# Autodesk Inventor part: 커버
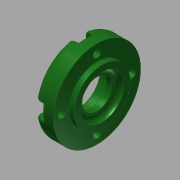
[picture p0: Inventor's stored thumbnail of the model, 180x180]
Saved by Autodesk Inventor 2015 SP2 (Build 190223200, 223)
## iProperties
Created: 2015-11
Part Number: 커버
Material: 알루미늄 6061
Document SubType Name: Modeling
Designer: mduedu
Density: 1 g/cm^3
Appearance: 매끄러움 - 짙은 산림 녹색
Author: mduedu
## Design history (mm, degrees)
sketch "스케치1"
  geometry: L1 (-7, 0)-(7, 0); L2 (-7, 0)-(-7, 25); L3 (-7, 25)-(4, 25); L4 (4, 25)-(4, 16); L5 (4, 16)-(7, 16); L6 (7, 16)-(7, 0); 2 further points
  constraints: 12 end point, 3 perpendicular, 2 parallel, 1 coincident, 1 horizontal, 1 midpoint
  dimensions: "d0" = 14 distance of L1.start L1.end; "d1" = 50 diameter of L3 L1; "d2" = 3 distance of L4.end L5.end; "d3" = 32 diameter of L5 L1
revolve "회전1" sketch "스케치1" stored, may be unused: angle "d4" = 90 deg
hole "구멍1" diameter "d7" = 25; stored, may be unused: countersink angle "d11" = 90 deg, drill point angle "d13" = 0 deg; dims "d5" = 10, "d6" = 10, "d8" = 6, "d9" = 4, "d10" = 2, "d12" = 3
hole "구멍2" diameter "d16" = 25; stored, may be unused: countersink angle "d20" = 90 deg, drill point angle "d22" = 0 deg; dims "d17" = 6, "d18" = 4, "d19" = 2, "d21" = 7.7, "d58" = 10, "d59" = 10
hole "구멍3" diameter "d25" = 17; stored, may be unused: countersink angle "d29" = 90 deg, drill point angle "d31" = 0 deg; dims "d23" = 10, "d24" = 10, "d26" = 6, "d27" = 4, "d28" = 2, "d30" = 4.2
chamfer "모따기1" distance "d32" = 0.6; stored, may be unused: second distance "d33" = 2, angle "d34" = 30 deg
fillet "모깎기1" dims "d35" = 0.3
fillet "모깎기2" dims "d36" = 3
fillet "모깎기3" dims "d37" = 3
fillet "모깎기4" dims "d38" = 0.3
sketch "스케치2" dims "d39" = 40
  geometry: 6 further points
  constraints: 2 vertical alignment, 1 coincident, 7 other
  dimensions: "d42" = 360 deg dimension on point (0, 0) point (0, 20) (derived)
sketch "스케치3"
  geometry: 4 further points
hole "구멍4" sketch "스케치3" at (-20, 0), (0, -20), (20, 0), (0, 20) diameter "d44" = 4.5; stored, may be unused: countersink angle "d48" = 90 deg, drill point angle "d50" = 0 deg; dims "d45" = 6, "d46" = 8, "d47" = 4.6, "d49" = 8
sketch "스케치4"
  geometry: L1 (-4, 0)-(-4, -4.678); L2 (4, 0)-(4, -4.678); A1 r 4 centre (0, 0) between (3.621, -1.7) and (-3.621, -1.7) reference; A2 r 25 centre (0, 20) between (-4, -4.678) and (4, -4.678) reference; 1 further point
  constraints: 4 end point, 4 point on circle, 2 tangent, 1 parallel, 1 vertical
extrude "돌출1" cut sketch "스케치4" stored distance "d51" = 0; taper "d52" = 0 deg
fillet "모깎기5" dims "d56" = 0.3
fillet "모깎기6" dims "d57" = 1
node "솔리드1"
pattern_circular "원형 패턴1" dims angle "d54" = 360 deg
